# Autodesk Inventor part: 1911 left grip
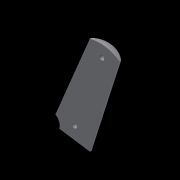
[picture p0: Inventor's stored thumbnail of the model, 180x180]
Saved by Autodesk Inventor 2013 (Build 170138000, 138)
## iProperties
Created: 2012-12
Part Number: 1911 left grip
Material: Generic
Document SubType Name: Modeling
Designer: John
Density: 1 g/cm^3
Author: John
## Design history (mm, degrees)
sketch "Sketch1"
  geometry: L1 (-53.04, -101.07)-(-35.834, -46.497) reference; L2 (-10.008, -33.299)-(0.762, -33.299); L3 (0.762, -9.83)-(-10.008, -9.83); L4 (0.762, -36.551)-(-22.268, -36.551) reference; L5 (15.748, -21.565)-(15.748, -19.304); L6 (67.564, -8.128)-(26.924, -8.128); L7 (-76.708, -32.918)-(-101.947, -93.849) reference; L8 (-101.947, -93.849)-(-53.04, -101.07) reference; L9 (67.564, -8.128)-(67.564, 5.867) reference; L10 (67.564, 5.867)-(9.144, 5.867) reference; L11 (9.144, 5.867)-(9.144, 11.43) reference; L12 (-81.119, 7.237)-(-80.862, 11.43); L13 (9.144, 11.43)-(-80.862, 11.43); L14 (-87.018, -8.028)-(-94.136, -5.079) reference; C1 r 2.553 at (0, 0) reference; C2 r 1.994 at (-95.123, -91.313) reference; C3 r 2 at (-75.514, 0.406) reference; C4 r 1.905 at (-85.547, -5.334) reference; C5 r 3.175 at (-30.302, -27.813); A1 r 11.735 centre (0.762, -21.565) between (0.762, -33.299) and (0.762, -9.83) reference; A2 r 14.986 centre (0.762, -21.565) between (0.762, -36.551) and (15.748, -21.565) reference; A3 r 11.735 centre (-10.008, -21.565) between (-10.008, -9.83) and (-10.008, -33.299) reference; A4 r 14.224 centre (-22.268, -50.775) between (-22.268, -36.551) and (-35.834, -46.497) reference; A5 r 11.176 centre (26.924, -19.304) between (26.924, -8.128) and (15.748, -19.304) reference; A6 r 8.763 centre (-89.865, 7.772) between (-88.554, -0.892) and (-81.119, 7.237) reference; A7 r 7.366 centre (-87.452, -8.175) between (-88.554, -0.892) and (-94.136, -5.079); A8 r 19.05 centre (-94.308, -25.628) between (-76.708, -32.918) and (-87.018, -8.028) reference; 3 further points
  constraints: 28 end point, 17 point on circle, 13 centre point, 13 tangent, 5 perpendicular, 2 coincident, 2 horizontal, 2 vertical, 1 midpoint, 1 parallel, 18 other
  dimensions: "d145" = 6.35 diameter of C5
extrude "Extrusion2" new body sketch "Sketch1" stored distance "d59" = 19.3548; taper "d60" = 0 deg
sketch "3D Sketch2"
sweep "Sweep2" sketch "3D Sketch2" dims "d62" = 0
sketch "Sketch4"
  geometry: L1 (-76.073, -16.93)-(-84.092, -1.85) reference; L2 (-74.409, -30.482)-(-81.214, -57.775) reference; L3 (-92.893, -13.174)-(-101.295, -13.174) reference; L4 (-77.94, -44.643)-(-90.574, -45.416); L5 (-90.574, -45.416)-(-82.294, -32.869); C1 r 1.905 at (-85.547, -5.334) reference; A1 r 19.05 centre (-92.893, -25.874) between (-74.409, -30.482) and (-76.073, -16.93) reference; A2 r 12.7 centre (-92.893, -25.874) between (-89.029, -13.776) and (-92.893, -13.174) reference; A3 r 35.814 centre (-88.437, -37.399) between (-84.092, -1.85) and (-98.411, -3.002) reference; A4 r 2.794 centre (-101.295, -10.38) between (-104.089, -10.38) and (-101.295, -13.174) reference; A5 r 2.794 centre (-101.295, -10.38) between (-104.087, -10.278) and (-101.295, -13.174); A6 r 7.874 centre (-96.219, -10.564) between (-98.411, -3.002) and (-104.087, -10.278) reference; A7 r 12.7 centre (-92.893, -25.874) between (-89.029, -13.776) and (-92.893, -13.174); A8 r 12.7 centre (-92.893, -25.874) between (-82.294, -32.869) and (-92.893, -13.174); 2 further points
  constraints: 18 point on circle, 10 end point, 9 centre point, 4 coincident, 2 concentric, 1 horizontal, 1 point on line, 1 tangent, 8 other
extrude "Extrusion3" join sketch "Sketch4" stored distance "d97" = 15.7226; taper "d98" = 0 deg
workplane "Work Plane1"
sketch "Sketch5"
  geometry: L1 (-7.861, 0)-(7.861, 0) reference; L2 (7.861, -12.018)-(7.861, 0) reference; L3 (-7.861, -12.018)-(7.861, -12.018) reference; L4 (-7.861, 0)-(-7.861, -12.018) reference; L5 (-3.937, 0)-(3.937, 0); L6 (-7.861, -12.018)-(-1.003, -12.018); L7 (0, 0)-(0, -8.629); A1 r 6.858 centre (-1.003, -6.199) between (-3.937, 0) and (-7.861, -6.199); A2 r 6.858 centre (1.003, -6.199) between (7.861, -6.199) and (3.937, 0); 1 further point
  constraints: 6 end point, 5 point on line, 4 point on circle, 2 centre point, 2 symmetric about line, 1 midpoint, 1 perpendicular, 2 other
extrude "Extrusion4" cut sketch "Sketch5" stored distance "d106" = 15.7226; taper "d107" = 0 deg
sketch "Sketch6"
  geometry: L1 (92.893, -13.174)-(101.295, -13.174) reference; L2 (94.719, -6.486)-(94.136, -5.079) reference; L3 (87.601, -9.435)-(94.719, -6.486) reference; L4 (101.295, -13.174)-(81.975, -13.174); A1 r 2.794 centre (101.295, -10.38) between (101.295, -13.174) and (104.087, -10.278) reference; A2 r 7.874 centre (96.219, -10.564) between (104.087, -10.278) and (98.411, -3.002) reference; A3 r 35.814 centre (88.437, -37.399) between (98.411, -3.002) and (90.909, -1.67) reference; A4 r 7.366 centre (87.452, -8.175) between (94.136, -5.079) and (90.909, -1.67) reference; 2 further points
  constraints: 2 end point, 1 collinear, 1 tangent, 2 other
extrude "Extrusion5" cut sketch "Sketch6" distance "d108" = 3.937; taper "d109" = 0 deg
mirror "Mirror1"
workplane "Work Plane2"
sweep "Sweep3" dims "d115" = 0
sweep "Sweep4" dims "d119" = 0
workplane "Work Plane3"
sweep "Sweep6" dims "d131" = 0
sketch "Sketch15"
  geometry: L1 (-20.851, -26.05)-(-20.851, -26.76) reference; L2 (-21.738, -21.901)-(-21.738, -26.76) reference; L3 (-25.508, -35.793)-(-26.989, -39.681); L4 (-26.989, -39.681)-(21.805, -39.681); L5 (21.805, -39.681)-(21.805, -10.457); L6 (21.805, -10.457)-(-11.471, -10.457); L7 (-11.471, -10.457)-(-21.738, -21.901); A1 r 15.328 centre (-22.268, -50.775) between (-24.079, -35.554) and (-25.508, -35.793) reference; A2 r 13.591 centre (-34.442, -26.76) between (-24.079, -35.554) and (-20.851, -26.76) reference; A3 r 11.735 centre (-10.008, -21.565) between (-21.738, -21.901) and (-20.851, -26.05) reference; A4 r 12.705 centre (-34.442, -26.76) between (-25.508, -35.793) and (-21.738, -26.76) reference; 1 further point
  constraints: 10 end point, 3 perpendicular
extrude "Extrusion6" cut sketch "Sketch15" stored distance "d132" = 37.338; taper "d133" = 0 deg
mirror "Mirror2"
workplane "Work Plane6"
sketch "Sketch21"
  geometry: L1 (0, 0)-(19.355, 0) reference; L2 (1.321, -3.607)-(1.321, 0); L3 (18.034, -3.607)-(18.034, 0); A1 r 10.389 centre (9.677, -3.607) between (0, -7.384) and (19.355, -7.384) reference; A2 r 8.357 centre (9.677, -3.607) between (1.321, -3.607) and (18.034, -3.607); 1 further point
  constraints: 4 end point, 2 point on circle, 2 point on line, 2 tangent, 1 centre point, 1 coincident, 1 parallel, 1 perpendicular
  dimensions: "d151" = 16.7132 diameter of A2
extrude "Extrusion7" cut sketch "Sketch21" stored distance "d152" = 37.338; taper "d153" = 0 deg
sketch "Sketch22"
  geometry: L1 (0, 5.563)-(19.355, 5.563) reference; L2 (0, 0)-(1.321, 0) reference; L3 (1.702, 0)-(1.702, 3.023); L4 (0, 3.023)-(1.702, 3.023); L5 (1.702, 0)-(0, 0); L6 (9.677, -3.607)-(9.677, 2.087); L7 (19.355, 3.023)-(17.653, 3.023); L8 (17.653, 0)-(17.653, 3.023); L9 (17.653, 0)-(19.355, 0); L10 (0, 3.023)-(0, 0); L11 (19.355, 3.023)-(19.355, 0); A1 r 8.357 centre (9.677, -3.607) between (1.321, -3.607) and (18.034, -3.607) reference; 1 further point
  constraints: 18 end point, 4 perpendicular, 3 symmetric about line, 1 collinear, 1 parallel
  dimensions: "d155" = 2.54 distance of L1.start L4.start
extrude "Extrusion8" cut sketch "Sketch22" stored distance "d156" = 37.338; taper "d157" = 0 deg
sweep "Sweep7" dims "d159" = 0
sketch "Sketch26"
  geometry: L1 (-94.719, -6.486)-(-94.136, -5.079); L2 (-87.601, -9.435)-(-94.719, -6.486); L3 (-87.601, -9.435)-(-94.579, -6.544) reference; L4 (-89.65, -13.174)-(-81.975, -13.174) reference; L5 (-92.893, -12.766)-(-102.748, -12.766) reference; L6 (-94.371, -4.976)-(-96.086, -9.116) reference; L7 (-96.086, -9.116)-(-95.709, -9.272) reference; L8 (-104.087, -10.278)-(-87.601, -9.435); A1 r 7.874 centre (-96.219, -10.564) between (-98.411, -3.002) and (-104.087, -10.278); A2 r 35.814 centre (-88.437, -37.399) between (-90.909, -1.67) and (-98.411, -3.002); A3 r 7.366 centre (-87.452, -8.175) between (-90.909, -1.67) and (-94.136, -5.079); A4 r 13.108 centre (-92.893, -25.874) between (-89.65, -13.174) and (-92.893, -12.766) reference; A5 r 2.794 centre (-101.295, -10.38) between (-104.087, -10.278) and (-102.748, -12.766) reference; A6 r 7.874 centre (-96.219, -10.564) between (-98.411, -3.002) and (-104.087, -10.278) reference; A7 r 35.814 centre (-88.437, -37.399) between (-91.5, -1.716) and (-98.411, -3.002) reference; A8 r 7.622 centre (-87.452, -8.175) between (-91.5, -1.716) and (-94.371, -4.976) reference; 1 further point
  constraints: 6 end point, 6 point on circle, 3 centre point, 2 other
extrude "Extrusion9" join sketch "Sketch26" stored distance "d160" = 7.8486; taper "d161" = 0 deg
sketch "Sketch27"
  geometry: L1 (0, 0)-(-41.219, -130.729); L2 (0, 0)-(137.073, 0); L3 (-55.804, 11.43)-(-98.449, -123.824); L4 (-79.932, 11.43)-(9.144, 11.43) reference; L5 (-89.574, -95.676)-(-61.783, -99.779); L6 (-61.783, -99.779)-(-26.719, 11.43); C1 r 1.994 at (-95.123, -91.313) reference
  constraints: 10 end point, 3 point on line, 1 equal length, 1 horizontal, 1 parallel
  dimensions: "d162" = 107.5 deg angle of L1 L2; "d165" = 28.0924 distance of L5.start L5.end
extrude "Extrusion10" cut sketch "Sketch27" stored distance "d166" = 13.9954; taper "d167" = 0 deg
workplane "Work Plane7"
sketch "Sketch28"
  geometry: C1 r 6.998 at (0, 0); 1 further point
  constraints: 1 centre point
  dimensions: "d169" = 13.9954 diameter of C1
extrude "Extrusion11" cut sketch "Sketch28" stored distance "d170" = 22.5171; taper "d171" = 0 deg
workplane "Work Plane8"
sketch "Sketch30"
  geometry: L1 (-10.008, -9.83)-(0.762, -9.83) reference; L2 (0.762, -33.299)-(-10.008, -33.299) reference; A1 r 11.735 centre (-10.008, -21.565) between (-10.008, -9.83) and (-21.742, -21.565) reference; A2 r 11.735 centre (0.762, -21.565) between (0.762, -33.299) and (1.099, -9.835) reference; A3 r 11.735 centre (-10.008, -21.565) between (-21.738, -21.901) and (-10.008, -33.299) reference; 1 further point
  constraints: 2 other
sweep "Sweep8" sketch "Sketch30" dims "d173" = 0
sketch "Sketch31"
  geometry: L1 (31.241, 6.452)-(41.564, 6.452); L2 (31.241, 6.452)-(31.241, -6.452); L3 (31.241, -6.452)-(41.564, -6.452); L4 (41.564, -6.452)-(41.564, 6.452); 7 further points; 2 other entities
  constraints: 8 end point, 2 horizontal, 1 perpendicular, 1 vertical, 2 other
  dimensions: "d174" = 6.4516 distance of point (31.241, 0) L1.start; "d175" = 12.9032 distance of L1.start L2.end
extrude "Extrusion12" cut sketch "Sketch31" distance "d176" = 2.159; taper "d177" = 0 deg
sketch "Sketch32"
  geometry: C1 r 2.54 at (-76.657, -84.049); C2 r 2.54 at (-49.2, -10.947)
  constraints: 2 centre point
  dimensions: "d180" = 5.08 diameter of C1; "d185" = 5.08 diameter of C2
extrude "Extrusion13" cut sketch "Sketch32" stored distance "d181" = 2.159; taper "d182" = 0 deg
sketch "Sketch33"
  geometry: L1 (-55.804, 11.43)-(-89.574, -95.676) reference; L2 (-82.294, -32.869)-(-90.574, -45.416) reference; L3 (-85.446, -45.102)-(-90.059, -45.384) reference; L4 (-90.574, -45.416)-(-90.059, -45.384) reference; L5 (-89.328, -43.527)-(-86.814, -45.186); 1 further point
  constraints: 2 end point, 2 point on line, 1 perpendicular
extrude "Extrusion14" cut sketch "Sketch33" distance "d186" = 25.4; taper "d187" = 0 deg
sketch "Sketch34"
  geometry: L1 (59.664, -100.092)-(101.947, -93.849) reference; L2 (92.046, -94.569)-(60.876, -99.275) reference; L3 (31.159, -5.307)-(60.937, -99.266) reference; L4 (61.169, -0.636)-(95.891, -84.128); C1 r 2.54 at (76.657, -84.049) reference; C2 r 2.54 at (49.2, -10.947) reference; A1 r 8.636 centre (100.167, -91.631) between (95.891, -84.128) and (92.334, -95.268); A2 r 34.544 centre (50.936, -33.629) between (61.169, -0.636) and (31.159, -5.307)
  constraints: 6 end point, 5 point on circle, 2 centre point, 2 point on line, 3 other
extrude "Extrusion15" join sketch "Sketch34" distance "d209" = 6.477; taper "d210" = 0 deg
workplane "Work Plane9"
workplane "Work Plane12"
workplane "Work Plane13"
loft "Loft1" dims "d219" = 0, "d220" = 90 deg, "d221" = 0, "d222" = 90 deg
workplane "Work Plane14"
sketch "Sketch39"
  geometry: L1 (0, 0)-(1.524, 0) reference; L2 (1.524, 0)-(9.15, -7.626); L3 (1.524, 0)-(12.309, 0); L4 (9.15, -7.626)-(9.15, 0); L5 (9.15, 0)-(1.524, 0); 1 further point
  constraints: 8 end point, 2 perpendicular, 1 equal length, 1 horizontal, 1 point on line
  dimensions: "d224" = 45 deg angle of L2 L3
extrude "Extrusion16" cut sketch "Sketch39" distance "d225" = 44.82993; taper "d226" = 0 deg
sketch "3D Sketch3"
sweep "Sweep9" sketch "3D Sketch3" dims "d228" = 0
mirror "Mirror3"
mirror "Mirror4"
sketch "Sketch41"
  geometry: L1 (-10.008, -32.408)-(0.762, -32.408) reference; L2 (-10.008, -10.721)-(0.762, -10.721) reference; L3 (-10.008, -10.721)-(-17.523, -10.721); L4 (-10.008, -32.408)-(-17.523, -32.408); A1 r 12.7 centre (-2.998, -21.565) between (-9.608, -10.721) and (-9.608, -32.408); A2 r 13.193 centre (-10.008, -21.565) between (-17.523, -10.721) and (-17.523, -32.408); 2 further points
  constraints: 4 end point, 4 point on circle, 2 centre point, 2 point on line, 1 coincident, 1 collinear, 1 parallel
extrude "Extrusion17" join sketch "Sketch41" stored distance "d230" = 5.7404; taper "d231" = 0 deg
sketch "Sketch43"
  geometry: A1 r 12.7 centre (-2.998, -21.565) between (-9.608, -10.721) and (-9.608, -32.408) reference; 1 further point
sweep "Sweep10" sketch "Sketch43" dims "d233" = 0
sketch "Sketch44"
  geometry: L1 (9.144, 8.89)-(9.144, 11.43) reference; L2 (9.144, 11.43)-(-79.932, 11.43) reference; L3 (9.144, 11.43)-(9.144, 11.176); L4 (9.144, 11.176)-(-89.177, 11.176); L5 (-89.177, 11.176)-(-89.177, 11.43); L6 (-89.177, 11.43)-(-79.932, 11.43); 1 further point
  constraints: 8 end point, 2 parallel, 2 point on line, 1 perpendicular
  dimensions: "d234" = 0.254 distance of L1.end L3.end
extrude "Extrusion18" cut sketch "Sketch44" stored distance "d235" = 5.7404; taper "d236" = 0 deg
sketch "Sketch45"
  geometry: L1 (18.034, 8.915)-(-1.321, 8.915) reference; L2 (-1.321, 6.629)-(-1.321, 8.915) reference; L3 (-1.321, 6.629)-(0.381, 6.629) reference; L4 (16.332, 6.629)-(18.034, 6.629) reference; L5 (18.034, 8.915)-(18.034, 6.629) reference; L6 (18.034, 6.629)-(17.78, 6.629); L7 (17.78, 6.629)-(17.78, 8.915); L8 (-1.321, 6.629)-(-1.067, 6.629); L9 (-1.067, 6.629)-(-1.067, 8.915); 1 further point
  constraints: 8 end point, 4 point on line, 2 perpendicular
  dimensions: "d237" = 0.254 distance of L4.end L6.end; "d238" = 0.254 distance of L2.start L8.end
extrude "Extrusion19" cut sketch "Sketch45" stored distance "d239" = 25.4; taper "d240" = 0 deg
sketch "Sketch47"
  geometry: L1 (-84.404, 0.406)-(-84.404, 18.681); L2 (-84.404, 18.681)-(-73.514, 18.681); L3 (-73.514, 9.068)-(-73.514, 18.681); C1 r 2 at (-75.514, 0.406) reference; A1 r 8.89 centre (-75.514, 0.406) between (-84.404, 0.406) and (-66.624, 0.406); A2 r 8.89 centre (-75.514, 0.406) between (-84.404, 0.406) and (-73.514, 9.068); 1 further point
  constraints: 6 end point, 5 point on circle, 2 centre point, 2 coincident, 2 perpendicular, 2 tangent, 1 vertical
extrude "Extrusion21" cut sketch "Sketch47" stored distance "d245" = 8.001; taper "d246" = 0 deg
sketch "Sketch51"
  geometry: C1 r 2.54 at (49.2, -10.947) reference; C2 r 2.54 at (76.657, -84.049) reference; C3 r 4.826 at (49.2, -10.947); C4 r 4.826 at (76.657, -84.049); 1 further point
  constraints: 2 centre point, 2 coincident
  dimensions: "d251" = 9.652 diameter of C3; "d252" = 9.652 diameter of C4
extrude "Extrusion22" join sketch "Sketch51" distance "d253" = 9.398; taper "d254" = 0 deg
mirror "Mirror5"
sketch "Sketch52"
  geometry: L1 (17.78, 8.915)-(-1.067, 8.915) reference; L2 (12.992, 3.321)-(12.992, 8.915); L3 (3.721, 3.321)-(3.721, 8.915); L4 (3.721, 8.915)-(12.992, 8.915); A1 r 8.357 centre (8.357, 0) between (0, 0) and (16.713, 0) reference; A2 r 5.702 centre (8.357, 0) between (3.721, 3.321) and (12.992, 3.321); 1 further point
  constraints: 6 end point, 2 point on circle, 2 point on line, 1 centre point, 1 coincident, 1 collinear, 1 perpendicular
extrude "Extrusion23" cut sketch "Sketch52" distance "d258" = 20.1168; taper "d259" = 0 deg
sketch "Sketch53"
  geometry: L1 (10.3, -7.696)-(10.3, -5.361); L2 (10.3, -7.696)-(6.414, -7.696); L3 (6.414, -7.696)-(6.414, -5.361); A1 r 5.702 centre (8.357, 0) between (3.721, 3.321) and (12.992, 3.321) reference; 1 further point
  constraints: 6 end point, 2 perpendicular, 2 point on circle
extrude "Extrusion24" cut sketch "Sketch53" distance "d263" = 13.7668; taper "d264" = 0 deg
sketch "Sketch54"
  geometry: L1 (12.992, 8.915)-(12.992, 3.321) reference; L2 (3.721, 8.915)-(12.992, 8.915); A1 r 8.839 centre (8.357, 16.442) between (3.721, 8.915) and (12.992, 8.915); 1 further point
  constraints: 2 end point, 2 point on circle, 1 centre point, 1 perpendicular
extrude "Extrusion25" cut sketch "Sketch54" distance "d266" = 34.925; taper "d267" = 0 deg
sketch "Sketch55"
  geometry: L1 (67.564, 5.867)-(-80.363, 5.867) reference; L2 (-20.469, -6.245)-(-10.008, -6.245); L3 (-20.469, -24.235)-(0, -24.235); A1 r 15.32 centre (-10.008, -21.565) between (-10.008, -6.245) and (-25.327, -21.565) reference; A2 r 8.995 centre (-20.469, -15.24) between (-20.469, -6.245) and (-20.469, -24.235) reference
  constraints: 4 end point, 3 tangent, 2 parallel, 2 point on circle, 1 centre point, 2 other
workplane "Work Plane17"
sketch "Sketch56"
  geometry: L1 (-8.995, 0)-(0, 0) reference; L2 (0, 0)-(0, 1.901); A1 r 22.225 centre (0, -20.324) between (0, 1.901) and (-8.995, 0); 1 further point
  constraints: 2 end point, 2 point on circle, 1 centre point
sweep "Sweep11" sketch "Sketch56" dims "d270" = 0
mirror "Mirror6"
sketch "Sketch57"
  geometry: L1 (-115.434, 30.265)-(169.147, 30.265); L2 (169.147, 30.265)-(169.147, -116.858); L3 (169.147, -116.858)-(-115.434, -116.858); L4 (-115.434, -116.858)-(-115.434, 30.265)
  constraints: 8 end point, 2 parallel, 1 horizontal, 1 perpendicular
extrude "Extrusion26" cut sketch "Sketch57" stored distance "d271" = 0; taper "d272" = 0 deg
body "Solid2"
sketch "Sketch3"
  geometry: L1 (0, 19.355)-(0, 0) reference; L2 (-49.437, 19.355)-(0, 19.355) reference; L3 (-49.437, 19.355)-(-49.437, 0) reference; L4 (0, 0)-(-49.437, 0) reference; A1 r 13.462 centre (-40.079, 9.677) between (-49.437, 19.355) and (-49.437, 0); 1 further point
  constraints: 2 point on circle, 1 centre point, 1 end point, 1 point on line
node "Projected Loop1"
sketch "Sketch7"
  geometry: L1 (-7.874, -1.702)-(-7.874, 0.419); L2 (-7.874, 0.419)-(7.861, 0.419); L3 (7.861, 0.419)-(7.861, -1.702); A1 r 19.037 centre (-0.006, -19.037) between (7.861, -1.702) and (-7.874, -1.702); 1 further point
  constraints: 6 end point, 2 point on circle, 1 centre point, 1 parallel, 1 perpendicular, 1 vertical
sketch "Sketch8"
  geometry: L1 (-86.303, -38.944)-(-82.294, -32.869) reference; L2 (-86.303, -38.944)-(-90.574, -45.416) reference; L3 (-92.893, -13.174)-(-101.295, -13.174) reference; L4 (-101.295, -13.174)-(-113.16, -13.174); A1 r 12.7 centre (-92.893, -25.874) between (-82.294, -32.869) and (-92.893, -13.174) reference; 1 further point
  constraints: 2 end point
sketch "Sketch10"
  geometry: L1 (-53.04, -101.07)-(-35.834, -46.497) reference; L2 (-22.268, -36.551)-(0.762, -36.551) reference; L3 (15.748, -21.565)-(15.748, -19.304) reference; L4 (26.924, -8.128)-(67.564, -8.128) reference; L5 (-53.04, -101.07)-(-58.066, -117.009); A1 r 14.224 centre (-22.268, -50.775) between (-22.268, -36.551) and (-35.834, -46.497) reference; A2 r 14.986 centre (0.762, -21.565) between (0.762, -36.551) and (15.748, -21.565) reference; A3 r 11.176 centre (26.924, -19.304) between (26.924, -8.128) and (15.748, -19.304) reference; 1 further point
  constraints: 2 end point, 1 collinear
sketch "Sketch11"
  geometry: L1 (0, 6.611)-(0, -0.578); L2 (0, -0.578)-(19.807, -0.578); L3 (19.355, 6.611)-(19.355, -0.578); A1 r 10.389 centre (9.677, 10.389) between (0, 6.611) and (19.355, 6.611); 1 further point
  constraints: 6 end point, 2 perpendicular, 2 point on circle, 1 centre point, 1 point on line, 1 vertical
sketch "Sketch12"
  geometry: L1 (0, 0)-(19.355, 0) reference; L2 (0, -15.697)-(19.355, -15.697) reference; L3 (0, -15.697)-(19.355, -15.697) reference; L4 (0, -12.112)-(0, -16.588); L5 (19.355, -16.588)-(19.355, -12.112); L6 (5.017, -16.588)-(5.017, -15.702); L7 (0, -16.588)-(5.017, -16.588); L8 (14.338, -16.588)-(14.338, -15.702); L9 (14.338, -16.588)-(19.355, -16.588); A1 r 12.7 centre (9.677, -3.888) between (0, -12.112) and (19.355, -12.112)
  constraints: 12 end point, 4 perpendicular, 4 point on circle, 1 centre point, 1 parallel
sketch "Sketch13"
  geometry: L1 (-10.008, -9.83)-(0.762, -9.83) reference; L2 (-21.742, -21.565)-(-21.742, -26.76); L3 (0.762, -9.83)-(27.888, -9.83); A1 r 11.735 centre (-10.008, -21.565) between (-10.008, -9.83) and (-21.742, -21.565); A2 r 14.224 centre (-22.268, -50.775) between (-28.7, -38.088) and (-35.834, -46.497); A3 r 12.7 centre (-34.442, -26.76) between (-28.7, -38.088) and (-21.742, -26.76); 3 further points
  constraints: 7 point on circle, 5 end point, 3 centre point, 2 perpendicular, 2 tangent, 1 coincident
node "Projected Loop2"
node "Projected Loop3"
sketch "Sketch23"
  geometry: L1 (0, 0)-(0, 19.355) reference; L2 (90.006, 0)-(0, 0) reference; L3 (0, 19.355)-(90.006, 19.355) reference; L4 (0.93, 0)-(-0.257, 0); L5 (-0.257, 0)-(-0.257, 19.355); L6 (-0.257, 19.355)-(0.93, 19.355); A1 r 50.8 centre (50.8, 9.677) between (0.93, 19.355) and (0.93, 0); 1 further point
  constraints: 6 end point, 2 parallel, 2 point on circle, 2 point on line, 1 centre point, 1 collinear
sketch "Sketch24"
  geometry: L1 (-81.017, 8.89)-(-80.862, 11.43) reference; L2 (-81.017, 8.89)-(-81.119, 7.237) reference; L3 (-94.719, -6.486)-(-94.136, -5.079) reference; L4 (-94.719, -6.486)-(-95.849, -9.214); A1 r 8.763 centre (-89.865, 7.772) between (-81.312, 5.867) and (-81.119, 7.237) reference; A2 r 8.763 centre (-89.865, 7.772) between (-88.554, -0.892) and (-81.312, 5.867) reference; A3 r 7.366 centre (-87.452, -8.175) between (-88.554, -0.892) and (-94.136, -5.079) reference; 1 further point
  constraints: 2 end point, 1 collinear
node "Projected Loop4"
sketch "Sketch29"
  geometry: L1 (-11.735, 0.012)-(-11.735, -9.334) reference; A1 r 12.7 centre (-23.544, -4.661) between (-11.735, -9.334) and (-11.735, 0.012); 1 further point
  constraints: 2 end point, 2 point on circle, 1 centre point
sketch "Sketch36"
  geometry: L1 (0, -38.046)-(1.524, -38.046); L2 (1.524, -38.046)-(1.524, 0); L3 (8.105, 0)-(8.105, -38.046); L4 (1.524, -38.046)-(1.524, -41.858); L5 (1.524, -41.858)-(8.105, -41.858); L6 (8.105, -41.858)-(8.105, -38.046); L7 (1.524, 0)-(1.524, 3.852); L8 (1.524, 3.852)-(8.105, 3.852); L9 (8.105, 3.852)-(8.105, 0); A1 r 39.007 centre (-32.53, -19.023) between (1.524, -38.046) and (1.524, 0); 1 further point
  constraints: 18 end point, 4 parallel, 2 perpendicular, 2 point on circle, 1 centre point
sketch "Sketch38"
  geometry: L1 (0, 0)-(1.524, 0); L2 (1.524, 0)-(1.524, -29.737); L3 (8.43, 0)-(8.43, -35.358); L4 (1.524, 0)-(1.524, 5.541); L5 (1.524, 5.541)-(8.43, 5.541); L6 (8.43, 5.541)-(8.43, 0); L7 (1.524, -29.737)-(1.524, -35.358); L8 (1.524, -35.358)-(8.43, -35.358); A1 r 24.793 centre (-18.316, -14.868) between (1.524, -29.737) and (1.524, 0); 1 further point
  constraints: 16 end point, 2 point on circle, 1 centre point, 1 parallel, 1 perpendicular
sketch "Sketch40"
  geometry: L1 (1.524, 0)-(1.524, 73.924) reference; L2 (0, 0)-(0, 98.565) reference; L3 (0, 98.565)-(0, 85.865); L4 (0, 98.565)-(0, 103.317); L5 (0, 103.317)-(11.176, 103.317); L6 (11.176, 103.317)-(11.176, 91.897); A1 r 12.7 centre (0, 85.865) between (11.176, 91.897) and (0, 98.565); A2 r 12.7 centre (0, 85.865) between (0, 73.165) and (1.524, 73.257); 1 further point
  constraints: 8 end point, 4 point on circle, 3 point on line, 2 centre point, 1 coincident, 1 parallel, 1 perpendicular
sketch "Sketch42"
  geometry: L1 (-6.649, -1.791)-(-5.613, -1.791); L2 (-5.613, -1.791)-(-5.613, -7.531); L3 (-5.613, -7.531)-(-6.649, -7.531); A1 r 4.775 centre (-10.465, -4.661) between (-6.649, -7.531) and (-6.649, -1.791); 1 further point
  constraints: 6 end point, 2 point on circle, 1 centre point
other parameters: "d99" = 90 deg, "d105" = 13.716, "d110" = 90 deg, "d120" = -39.6875, "d168" = 90 deg, "d202" = 17.272, "d208" = 69.088, "d223" = 90 deg
